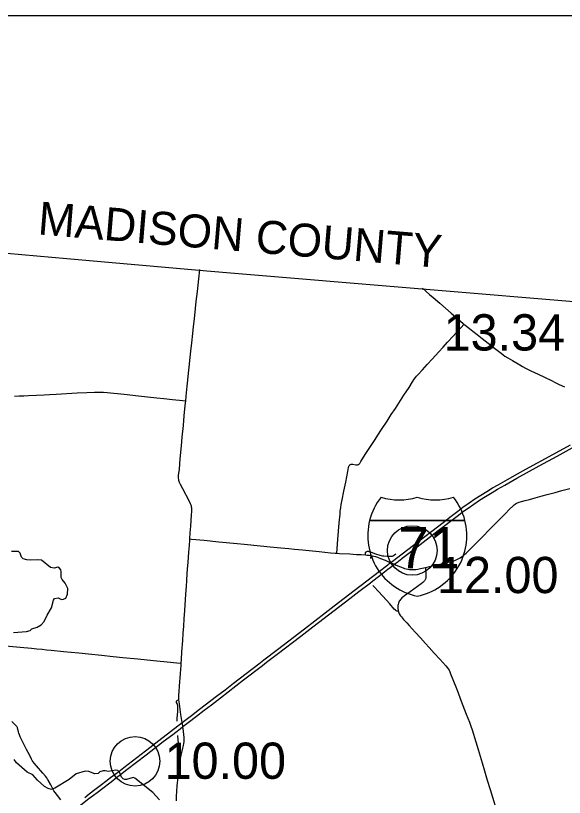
# Model space of a CAD drawing. Extents: x 1597222 to 1925846, y 496284 to 911751.
# Drawn here: x 1680799 to 1697422, y 607664 to 631367 of the extents above; entities that cross this region are included whole.
import ezdxf

# ---------------------------------------------------------------- set-up
doc = ezdxf.new("R2010")
doc.units = 0
for name, color, linetype in [('Default', 7, 'Continuous'), ('GM_X_Adjacent_County_Text', 7, 'Continuous'), ('GM_X_County', 7, 'Continuous'), ('GM_X_County_Road', 7, 'Continuous'), ('GM_X_Interstate_Route', 7, 'Continuous'), ('GM_X_Interstate_Shield', 7, 'Continuous'), ('GM_X_Township', 7, 'Continuous'), ('GM_X_Township_Road', 7, 'Continuous'), ('SC_Scratch1', 7, 'Continuous')]:
    doc.layers.add(name, color=color, linetype=linetype)

msp = doc.modelspace()

# ---------------------------------------------------------------- linework, layer by layer
at = {"layer": 'Default'}
for centre in [(1692814, 615150), (1692814, 615150), (1684417, 608759), (1684417, 608759)]:
    msp.add_circle(centre, 750, dxfattribs=at)
at = {"layer": 'GM_X_County'}
msp.add_lwpolyline([(1641954, 604485), (1642314, 608472), (1642473, 610227), (1643260, 618938), (1643522, 621830), (1644023, 627376), (1646278, 627176), (1649675, 626876), (1652057, 626672), (1654722, 626423), (1661976, 625747), (1675318, 624618), (1678685, 624323), (1679159, 624282), (1682349, 624003), (1686356, 623652), (1687189, 623580), (1693117, 623083), (1698190, 622658)], dxfattribs=at)
at = {"layer": 'GM_X_County_Road'}
for points in [[(1685952, 619687), (1685965, 619825), (1685998, 620135), (1686016, 620314), (1686038, 620527), (1686057, 620706), (1686088, 621000), (1686109, 621196), (1686136, 621441), (1686167, 621734), (1686190, 621946), (1686214, 622175), (1686247, 622485), (1686270, 622697), (1686305, 623007), (1686344, 623382), (1686376, 623666)], [(1680763, 619828), (1680909, 619835), (1681043, 619842), (1681185, 619850), (1681431, 619861), (1681660, 619874), (1681824, 619882), (1682028, 619893), (1682659, 619926), (1682953, 619941), (1683183, 619952), (1683298, 619955), (1683380, 619954), (1683462, 619949), (1683576, 619939), (1684082, 619885), (1684522, 619840), (1684794, 619811), (1685077, 619780), (1685287, 619758), (1685549, 619731), (1685859, 619697), (1685946, 619687), (1685952, 619687)], [(1686074, 615500), (1686087, 615686), (1686102, 615889), (1686128, 616233), (1686134, 616331), (1686136, 616396), (1686134, 616429), (1686130, 616461), (1686123, 616492), (1686113, 616523), (1686094, 616568), (1686051, 616656), (1685862, 617021), (1685795, 617152), (1685767, 617212), (1685755, 617243), (1685745, 617275), (1685738, 617307), (1685735, 617340), (1685734, 617373), (1685737, 617423), (1685758, 617619), (1685786, 617929), (1685822, 618322), (1685846, 618583), (1685880, 618943), (1685907, 619237), (1685939, 619547), (1685952, 619687)], [(1693218, 614638), (1693420, 614684), (1693645, 614733), (1693901, 614791), (1694012, 614818), (1694075, 614838), (1694121, 614855), (1694166, 614875), (1694225, 614904), (1694268, 614929), (1694309, 614956), (1694362, 614994), (1694400, 615025), (1694449, 615069), (1694508, 615126), (1694658, 615277), (1694980, 615605), (1695118, 615745), (1695408, 616036), (1695489, 616118), (1695626, 616258), (1695765, 616398), (1695857, 616491), (1695905, 616536), (1695931, 616557), (1695944, 616566), (1695973, 616582), (1696003, 616595), (1696049, 616612), (1696128, 616635), (1696239, 616665), (1696365, 616699), (1696540, 616747), (1696745, 616802), (1696903, 616846), (1697141, 616909), (1697347, 616966), (1697585, 617029)], [(1685813, 611733), (1685820, 611845), (1685836, 612074), (1685860, 612418), (1685877, 612647), (1685891, 612860), (1685906, 613073), (1685924, 613335), (1685959, 613826), (1685975, 614055), (1685987, 614235), (1686000, 614449), (1686010, 614579), (1686024, 614792), (1686046, 615103), (1686061, 615300), (1686071, 615464), (1686074, 615500)], [(1686074, 615500), (1686089, 615499), (1686123, 615496), (1686515, 615459), (1686956, 615415), (1687283, 615382), (1687511, 615361), (1687723, 615339), (1688213, 615291), (1688507, 615263), (1688834, 615230), (1689079, 615206), (1689242, 615191), (1689487, 615166), (1689993, 615117), (1690336, 615082), (1690483, 615068), (1690534, 615065)], [(1691393, 615018), (1691398, 615055), (1691400, 615072), (1691402, 615085), (1691405, 615095), (1691412, 615104), (1691425, 615114), (1691439, 615122), (1691454, 615127), (1691470, 615128), (1691487, 615126), (1691503, 615123), (1691519, 615118), (1691705, 615053), (1691829, 615011), (1691877, 614998), (1691909, 614992), (1691958, 614987), (1692056, 614982), (1692187, 614974), (1692204, 614976), (1692220, 614980), (1692234, 614986), (1692248, 614995), (1692275, 615015), (1692314, 615044)], [(1690534, 615065), (1690614, 615059), (1690925, 615044), (1691121, 615033), (1691269, 615024), (1691393, 615018)], [(1691393, 615018), (1691452, 615012), (1691508, 615006), (1691567, 614999)], [(1691567, 614999), (1691608, 614991), (1691655, 614980), (1691703, 614966), (1691765, 614945), (1691856, 614910), (1691993, 614853), (1692160, 614780), (1692273, 614731), (1692324, 614709), (1692460, 614651), (1692536, 614621), (1692583, 614606), (1692630, 614593), (1692678, 614583), (1692727, 614575), (1692776, 614571), (1692825, 614570), (1692874, 614572), (1692923, 614577), (1692988, 614587), (1693068, 614603), (1693218, 614638)], [(1679890, 612324), (1679970, 612317), (1680117, 612302), (1680606, 612252), (1680932, 612220), (1681275, 612186), (1681438, 612169), (1681601, 612153), (1681731, 612140), (1681878, 612125), (1682253, 612088), (1682482, 612065), (1682710, 612042), (1683004, 612013), (1683395, 611975), (1683754, 611938), (1684048, 611910), (1684504, 611863), (1684782, 611838), (1685075, 611809), (1685385, 611778), (1685679, 611748), (1685807, 611734), (1685813, 611733)], [(1685763, 611033), (1685791, 611419), (1685809, 611665), (1685813, 611733)], [(1685743, 610622), (1685745, 610764), (1685751, 610879), (1685763, 611033)], [(1685683, 609976), (1685689, 609991), (1685692, 610007), (1685696, 610039), (1685705, 610185), (1685708, 610234), (1685717, 610364), (1685717, 610397), (1685716, 610413), (1685714, 610429), (1685710, 610445), (1685706, 610461), (1685701, 610476), (1685688, 610506), (1685675, 610537), (1685673, 610544), (1685671, 610552), (1685670, 610561), (1685670, 610569), (1685671, 610577), (1685674, 610584), (1685678, 610592), (1685683, 610597), (1685690, 610603), (1685699, 610607), (1685743, 610622)], [(1685815, 608945), (1685865, 609154), (1685883, 609234), (1685894, 609299), (1685900, 609347), (1685904, 609396), (1685905, 609445), (1685903, 609494), (1685898, 609559), (1685883, 609673), (1685863, 609809), (1685859, 609836), (1685844, 609931), (1685834, 609998), (1685807, 610177), (1685760, 610502), (1685743, 610622)], [(1685815, 608945), (1685787, 608959), (1685778, 608964), (1685771, 608971), (1685766, 608977), (1685762, 608984), (1685759, 608992), (1685757, 609000), (1685752, 609032), (1685739, 609214), (1685724, 609411), (1685714, 609543)], [(1685735, 608478), (1685745, 608600), (1685754, 608682), (1685765, 608747), (1685783, 608827), (1685800, 608891), (1685815, 608945)], [(1685678, 607794), (1685682, 607849), (1685696, 608012), (1685718, 608273), (1685732, 608453), (1685735, 608478)], [(1685672, 607557), (1685673, 607619), (1685676, 607750), (1685678, 607794)]]:
    msp.add_lwpolyline(points, dxfattribs=at)
at = {"layer": 'GM_X_Interstate_Route'}
for points in [[(1697205, 618011), (1697839, 618362), (1697921, 618407)], [(1682895, 607664), (1683030, 607770), (1683202, 607901), (1683400, 608056), (1683534, 608157), (1683674, 608264), (1683811, 608370), (1683920, 608452), (1684077, 608575), (1684860, 609176), (1685133, 609387), (1685844, 609931), (1686127, 610149), (1686373, 610339), (1686880, 610728), (1687142, 610927), (1687400, 611127), (1688171, 611718), (1688319, 611832), (1688728, 612146), (1689547, 612776), (1690175, 613258), (1690446, 613467), (1691059, 613935), (1691824, 614525), (1692072, 614713), (1692109, 614741), (1692139, 614764), (1692160, 614780), (1692206, 614815), (1692332, 614914), (1692851, 615314), (1693749, 616003), (1693996, 616194), (1694192, 616343), (1694351, 616459), (1694538, 616592), (1694714, 616712), (1694893, 616827), (1695075, 616942), (1695243, 617045), (1695412, 617143), (1695699, 617304), (1695999, 617470), (1696258, 617613), (1697076, 618065), (1697608, 618358)], [(1692509, 614914), (1692962, 615262), (1693600, 615752), (1694173, 616191), (1694370, 616338), (1694503, 616434), (1694679, 616556), (1694856, 616674), (1695036, 616790), (1695231, 616911), (1695400, 617011), (1695614, 617133), (1695987, 617339), (1696662, 617712), (1697205, 618011)], [(1692346, 614787), (1692494, 614902), (1692509, 614914)], [(1691978, 614504), (1692079, 614582), (1692254, 614716), (1692273, 614731), (1692300, 614752), (1692346, 614787)], [(1691567, 614189), (1691978, 614504)], [(1686279, 610129), (1686510, 610306), (1686731, 610475), (1687004, 610686), (1687700, 611226), (1688279, 611665), (1688402, 611759), (1688721, 612005), (1689437, 612554), (1689802, 612833), (1690921, 613693), (1691194, 613903), (1691545, 614172), (1691567, 614189)], [(1686028, 609936), (1686275, 610126), (1686279, 610129)], [(1685781, 609746), (1685863, 609809), (1686028, 609936)], [(1685270, 609354), (1685558, 609575), (1685651, 609646)], [(1685651, 609646), (1685781, 609746)], [(1683742, 608180), (1683816, 608236), (1683972, 608358), (1684167, 608508), (1684752, 608957), (1685270, 609354)], [(1682766, 607431), (1682877, 607516), (1683018, 607625), (1683161, 607734), (1683266, 607816), (1683436, 607946), (1683648, 608108), (1683742, 608180)]]:
    msp.add_lwpolyline(points, dxfattribs=at)
at = {"layer": 'GM_X_Interstate_Shield'}
for p, q in [((1691523, 616061), (1694408, 616061)), ((1694408, 616061), (1691523, 616061)), ((1694408, 616061), (1691523, 616061))]:
    msp.add_line(p, q, dxfattribs=at)
for centre, start, end in [((1693341, 615601), 141.669, 165.8066), ((1692418, 618557), 253.0091, 286.9909), ((1693514, 618557), 253.0091, 286.9909), ((1692591, 615601), 14.1934, 38.331), ((1693341, 615601), 165.8066, 258.463), ((1692591, 615601), 281.537, 14.1934)]:
    msp.add_arc(centre, 1875, start, end, dxfattribs=at)
at = {"layer": 'GM_X_Township'}
for points in [[(1680735, 612663), (1681130, 612695), (1681242, 612727), (1681294, 612777), (1681455, 612828), (1681569, 612896), (1681667, 612998), (1681752, 613193), (1681888, 613415), (1681947, 613640), (1681981, 613694), (1682087, 613712), (1682193, 613663), (1682253, 613671), (1682321, 613709), (1682372, 613823), (1682382, 613998), (1682300, 614162), (1682208, 614273), (1682182, 614335), (1682178, 614504), (1682164, 614560), (1682126, 614618), (1682074, 614642), (1681966, 614614), (1681852, 614635), (1681578, 614860), (1681456, 614868), (1681246, 614852), (1681135, 614863), (1681025, 614895), (1680975, 614945), (1680935, 615066), (1680881, 615116), (1680673, 615122)], [(1685162, 607590), (1684958, 607809), (1684410, 608251), (1684356, 608267), (1684154, 608210), (1684104, 608204), (1684053, 608222), (1684003, 608274), (1683953, 608405), (1683944, 608431), (1683892, 608475), (1683832, 608489), (1683611, 608447), (1683507, 608469), (1683453, 608466), (1683353, 608438), (1683301, 608390), (1683194, 608382), (1683014, 608444), (1682902, 608459), (1682634, 608375), (1682419, 608211), (1681990, 607945), (1681927, 607921), (1681886, 607905), (1681780, 607934), (1681670, 607992), (1681464, 608183), (1681318, 608345), (1681152, 608430), (1680827, 608709), (1680754, 608812)]]:
    msp.add_lwpolyline(points, dxfattribs=at)
at = {"layer": 'GM_X_Township_Road'}
for points in [[(1693123, 623099), (1693339, 622915), (1693447, 622819), (1693645, 622647), (1693993, 622346), (1694192, 622174), (1694354, 622035), (1694381, 622013)], [(1690534, 615065), (1690534, 615071), (1690564, 615480), (1690605, 615987), (1690626, 616249), (1690635, 616347), (1690649, 616445), (1690665, 616542), (1690694, 616687), (1690745, 616944), (1690799, 617218), (1690832, 617379), (1690863, 617540), (1690887, 617670), (1690895, 617702), (1690901, 617717), (1690909, 617731), (1690919, 617743), (1690931, 617754), (1690945, 617762), (1690961, 617766), (1690977, 617768), (1690993, 617767), (1691010, 617766), (1691108, 617750), (1691141, 617749), (1691157, 617750), (1691172, 617755), (1691186, 617761), (1691200, 617770), (1691211, 617781), (1691222, 617794), (1691232, 617808), (1691258, 617850), (1691391, 618057), (1691489, 618209), (1691686, 618511), (1691776, 618648), (1691883, 618814), (1692053, 619075), (1692179, 619268), (1692304, 619460), (1692456, 619694), (1692564, 619859), (1692716, 620093), (1692822, 620259), (1692876, 620341), (1692915, 620394), (1692946, 620432), (1692989, 620482), (1693122, 620627), (1693266, 620785), (1693420, 620954), (1693619, 621173), (1693752, 621318), (1693884, 621464), (1694050, 621646), (1694204, 621817), (1694293, 621913), (1694375, 622006), (1694381, 622013)], [(1694381, 622013), (1694456, 621952), (1694546, 621881), (1694650, 621801), (1694779, 621700), (1694936, 621579), (1695116, 621438), (1695310, 621286), (1695504, 621133), (1695569, 621083), (1695623, 621046), (1695707, 620995), (1695848, 620910), (1696073, 620774), (1696158, 620725), (1696246, 620680), (1696408, 620600), (1696630, 620494), (1696822, 620400), (1697029, 620300), (1697147, 620243), (1697266, 620187), (1697430, 620111)], [(1691561, 614908), (1691567, 614995), (1691567, 614999)], [(1693218, 614638), (1693219, 614629), (1693225, 614422), (1693227, 614356), (1693227, 614340), (1693225, 614324), (1693222, 614308), (1693218, 614292), (1693212, 614277), (1693206, 614262), (1693198, 614247), (1693189, 614234), (1693180, 614220), (1693158, 614196), (1693133, 614175), (1693080, 614136), (1692747, 613899), (1692575, 613775), (1692524, 613734), (1692500, 613713), (1692477, 613689), (1692456, 613664), (1692438, 613637), (1692421, 613609), (1692408, 613579), (1692396, 613548), (1692388, 613517), (1692381, 613485), (1692378, 613452), (1692376, 613420), (1692377, 613387), (1692383, 613345), (1692388, 613318)], [(1692388, 613318), (1692364, 613314), (1692345, 613313), (1692330, 613318), (1692316, 613326), (1692304, 613337), (1692271, 613373), (1692130, 613533), (1691921, 613763), (1691777, 613920), (1691666, 614041), (1691621, 614087)], [(1692388, 613318), (1692408, 613258), (1692422, 613228), (1692439, 613200), (1692457, 613172), (1692487, 613134), (1692553, 613060), (1692650, 612954)], [(1692650, 612954), (1692719, 612878), (1692906, 612671), (1693059, 612500), (1693213, 612330), (1693324, 612209), (1693479, 612039), (1693646, 611858), (1693833, 611651), (1693876, 611601), (1693904, 611561), (1693929, 611519), (1693951, 611475), (1693977, 611415), (1694130, 611016), (1694200, 610832), (1694265, 610664), (1694346, 610449), (1694448, 610189), (1694544, 609945), (1694590, 609822), (1694627, 609713), (1694738, 609352), (1694809, 609116), (1694930, 608707), (1695003, 608472), (1695088, 608189), (1695172, 607906), (1695243, 607670), (1695353, 607309)], [(1680799, 609852), (1680688, 609965)], [(1681799, 608162), (1681793, 608173), (1681768, 608216), (1681741, 608256), (1681701, 608308), (1681627, 608395), (1681434, 608619), (1681359, 608705), (1681329, 608744), (1681301, 608785), (1681277, 608827), (1681225, 608929), (1681128, 609119), (1680967, 609441), (1680939, 609500), (1680914, 609561), (1680898, 609607), (1680885, 609654), (1680860, 609766), (1680855, 609782), (1680848, 609796), (1680839, 609810), (1680829, 609823), (1680805, 609846), (1680799, 609852)], [(1681929, 607921), (1681860, 608042), (1681799, 608162)], [(1682164, 607590), (1682063, 607721), (1681996, 607813), (1681959, 607867), (1681929, 607921)]]:
    msp.add_lwpolyline(points, dxfattribs=at)
at = {"layer": 'SC_Scratch1'}
msp.add_lwpolyline([(1597222, 631367), (1793472, 631367), (1793472, 496867), (1597222, 496867)], close=True, dxfattribs=at)

# ---------------------------------------------------------------- texts
at = {"layer": 'Default'}
for s, p in [('13.34', (1693764, 621213)), ('13.34', (1693764, 621213)), ('12.00', (1693564, 613857)), ('12.00', (1693564, 613857)), ('10.00', (1685310, 608226)), ('10.00', (1685310, 608226))]:
    msp.add_text(s, height=1100, dxfattribs=at).set_placement(p)
at = {"layer": 'GM_X_Adjacent_County_Text'}
msp.add_text('MADISON COUNTY', height=1000, rotation=355.2269, dxfattribs=at).set_placement((1681452, 624735))
at = {"layer": 'GM_X_Interstate_Shield'}
msp.add_text('71', height=1250, dxfattribs=at).set_placement((1692388, 614608))

doc.saveas('drawing.dxf')
